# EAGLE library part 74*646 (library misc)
74xx646DW Octal transceiver/register with 3-state outputs (SOIC24)
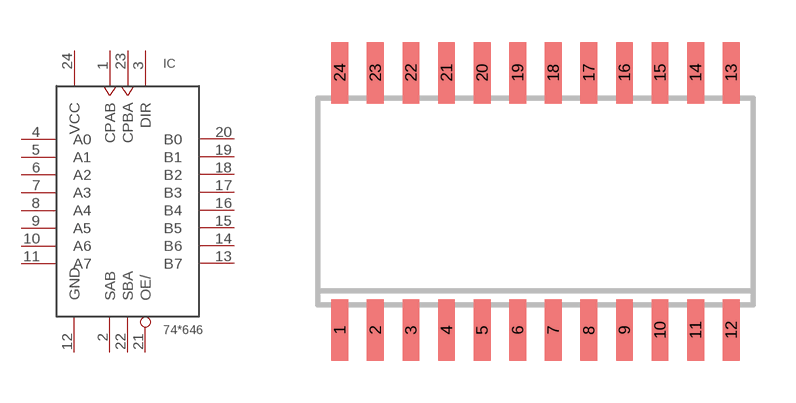
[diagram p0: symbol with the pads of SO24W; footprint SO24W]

Designator prefix IC

## 74646DW  [SO24W]
1  CPAB  in
2  SAB  in
3  DIR  in
4  A0
5  A1
6  A2
7  A3
8  A4
9  A5
10  A6
11  A7
12  GND  sup
13  B7
14  B6
15  B5
16  B4
17  B3
18  B2
19  B1
20  B0
21  OE/  in
22  SBA  in
23  CPBA  in
24  VCC  sup

## Footprint SO24W (pad centres in mm)
smd 0.6 x 2.2: 1 -6.985,-4.6; 2 -5.715,-4.6; 3 -4.445,-4.6; 4 -3.175,-4.6; 5 -1.905,-4.6; 6 -0.635,-4.6; 7 0.635,-4.6; 8 1.905,-4.6; 9 3.175,-4.6; 10 4.445,-4.6; 11 5.715,-4.6; 12 6.985,-4.6; 13 6.985,4.6; 14 5.715,4.6; 15 4.445,4.6; 16 3.175,4.6; 17 1.905,4.6; 18 0.635,4.6; 19 -0.635,4.6; 20 -1.905,4.6; 21 -3.175,4.6; 22 -4.445,4.6; 23 -5.715,4.6; 24 -6.985,4.6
